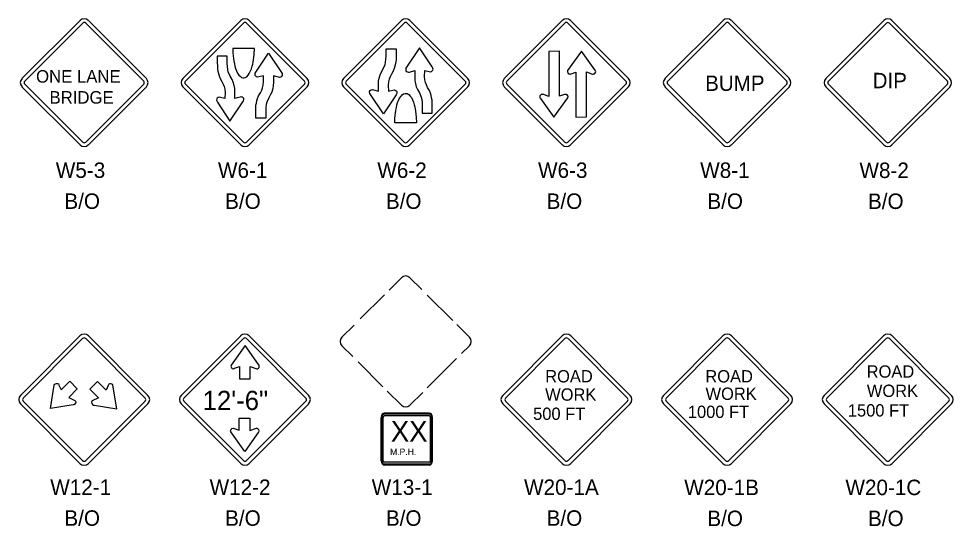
# Model space of a CAD drawing. Extents: x 10000 to 10794, y 10000 to 10499.
# Drawn here: x 10289.1 to 10500.7, y 10279.5 to 10394.4 of the extents above; entities that cross this region are included whole.
import ezdxf

# ---------------------------------------------------------------- set-up
doc = ezdxf.new("R2010")
doc.units = 0
for name, color, linetype in [('DSIndex', 7, 'Continuous'), ('DSText', 7, 'Continuous'), ('DSTitle', 7, 'Continuous'), ('PlotBorder_dp', 7, 'Continuous')]:
    doc.layers.add(name, color=color, linetype=linetype)

msp = doc.modelspace()

# ---------------------------------------------------------------- linework, layer by layer
at = {"layer": 'DSIndex'}
for p, q in [((10339.42, 10394.02), (10326.27, 10380.87)), ((10354.44, 10380.87), (10341.29, 10394.02)), ((10362.67, 10380.87), (10375.81, 10394.02)), ((10377.69, 10394.02), (10390.84, 10380.87)), ((10399.07, 10380.87), (10412.21, 10394.02)), ((10414.08, 10394.02), (10427.23, 10380.87)), ((10340.01, 10393.41), (10326.89, 10380.28)), ((10353.82, 10380.28), (10340.69, 10393.41)), ((10363.29, 10380.28), (10376.41, 10393.41)), ((10377.09, 10393.41), (10390.22, 10380.28)), ((10399.68, 10380.28), (10412.81, 10393.41)), ((10413.49, 10393.41), (10426.62, 10380.28)), ((10326.89, 10379.6), (10340.01, 10366.47)), ((10340.69, 10366.47), (10353.82, 10379.6)), ((10376.41, 10366.47), (10363.29, 10379.6)), ((10390.22, 10379.6), (10377.09, 10366.47)), ((10412.81, 10366.47), (10399.68, 10379.6)), ((10426.62, 10379.6), (10413.49, 10366.47)), ((10326.27, 10379), (10339.42, 10365.86)), ((10341.29, 10365.86), (10354.44, 10379)), ((10375.81, 10365.86), (10362.67, 10379.01)), ((10390.84, 10379), (10377.69, 10365.86)), ((10412.21, 10365.86), (10399.07, 10379)), ((10427.23, 10379), (10414.08, 10365.86)), ((10373, 10332.98), (10375.79, 10335.77)), ((10377.71, 10335.77), (10380.41, 10333.07)), ((10366.45, 10326.43), (10371.93, 10331.91)), ((10381.63, 10331.85), (10387.41, 10326.07)), ((10362.32, 10322.3), (10365.08, 10325.05)), ((10388.3, 10325.18), (10391.18, 10322.3)), ((10289.53, 10309.13), (10303, 10322.61)), ((10290.15, 10308.52), (10303.61, 10321.98)), ((10304.31, 10321.98), (10317.77, 10308.52)), ((10304.92, 10322.61), (10318.39, 10309.13)), ((10325.92, 10309.13), (10339.4, 10322.61)), ((10326.55, 10308.52), (10340.01, 10321.98)), ((10340.7, 10321.98), (10354.16, 10308.52)), ((10341.31, 10322.61), (10354.79, 10309.13)), ((10364.78, 10317.92), (10362.32, 10320.38)), ((10391.18, 10320.38), (10389.38, 10318.58)), ((10371.6, 10311.1), (10365.97, 10316.73)), ((10388.29, 10317.48), (10381.65, 10310.85)), ((10375.79, 10306.91), (10372.59, 10310.11)), ((10380.62, 10309.82), (10377.71, 10306.91)), ((10303, 10293.74), (10289.53, 10307.22)), ((10303.61, 10294.37), (10290.15, 10307.83)), ((10317.77, 10307.83), (10304.31, 10294.37)), ((10318.39, 10307.22), (10304.92, 10293.74)), ((10339.4, 10293.74), (10325.92, 10307.22)), ((10340.01, 10294.37), (10326.55, 10307.83)), ((10354.16, 10307.83), (10340.7, 10294.37)), ((10354.79, 10307.22), (10341.31, 10293.74)), ((10382.1, 10305.13), (10371.91, 10305.13)), ((10371.19, 10294.33), (10371.19, 10304.15)), ((10371.37, 10294.33), (10371.37, 10304.15)), ((10371.67, 10294.33), (10371.67, 10304.15)), ((10382.1, 10304.88), (10371.91, 10304.88)), ((10382.1, 10304.47), (10371.91, 10304.47)), ((10382.35, 10294.33), (10382.35, 10304.15)), ((10382.65, 10294.33), (10382.65, 10304.15)), ((10382.83, 10294.33), (10382.83, 10304.15)), ((10382.1, 10294), (10371.91, 10294)), ((10382.1, 10293.59), (10371.91, 10293.59)), ((10382.1, 10293.35), (10371.91, 10293.35))]:
    msp.add_line(p, q, dxfattribs=at)
for points in [[(10342.49, 10387.67), (10337.6, 10387.67), (10337.61, 10387.36), (10337.64, 10386.8), (10337.7, 10385.96), (10337.75, 10385.49), (10337.84, 10384.81), (10337.96, 10384.25), (10338.08, 10383.63), (10338.24, 10383.1), (10338.48, 10382.62), (10338.68, 10382.1), (10339.01, 10381.66), (10339.24, 10381.39), (10339.57, 10381.11), (10339.85, 10381.04), (10340.08, 10381.04), (10340.39, 10381.1), (10340.79, 10381.28), (10341.05, 10381.64), (10341.35, 10382), (10341.57, 10382.48), (10341.82, 10383.03), (10341.98, 10383.66), (10342.13, 10384.12), (10342.22, 10384.56), (10342.32, 10385.06), (10342.38, 10385.72), (10342.44, 10386.4)], [(10372.31, 10387.61), (10374.57, 10387.61), (10374.57, 10385.89), (10374.56, 10385.55), (10374.56, 10385.04), (10374.53, 10384.69), (10374.43, 10384.18), (10374.31, 10383.64), (10374.16, 10383.13), (10373.94, 10382.52), (10373.51, 10381.82), (10373.24, 10381.25), (10373.04, 10380.72), (10372.87, 10380.11), (10372.82, 10379.35), (10372.85, 10377.99), (10374.18, 10378.3), (10374.4, 10378.21), (10374.58, 10378.08), (10374.72, 10377.91), (10374.75, 10377.64), (10374.72, 10377.45), (10374.56, 10377.15), (10371.71, 10372.87), (10368.61, 10377.46), (10368.58, 10377.76), (10368.58, 10377.96), (10368.68, 10378.16), (10368.94, 10378.3), (10369.21, 10378.37), (10369.43, 10378.32), (10370.58, 10377.98), (10370.58, 10379.42), (10370.63, 10380.28), (10370.75, 10380.91), (10370.95, 10381.69), (10371.21, 10382.26), (10371.65, 10383.03), (10372.09, 10384.01), (10372.21, 10384.52), (10372.29, 10385.23), (10372.31, 10385.91)], [(10380.51, 10373.04), (10382.78, 10373.04), (10382.78, 10374.76), (10382.77, 10375.1), (10382.77, 10375.61), (10382.73, 10375.96), (10382.63, 10376.47), (10382.51, 10377.01), (10382.36, 10377.52), (10382.14, 10378.13), (10381.72, 10378.83), (10381.45, 10379.4), (10381.24, 10379.93), (10381.07, 10380.54), (10381.02, 10381.3), (10381.05, 10382.66), (10382.38, 10382.35), (10382.6, 10382.44), (10382.78, 10382.57), (10382.92, 10382.74), (10382.95, 10383.01), (10382.92, 10383.2), (10382.77, 10383.5), (10379.91, 10387.78), (10376.82, 10383.19), (10376.79, 10382.89), (10376.79, 10382.69), (10376.89, 10382.49), (10377.14, 10382.35), (10377.41, 10382.28), (10377.63, 10382.33), (10378.79, 10382.67), (10378.79, 10381.23), (10378.84, 10380.37), (10378.95, 10379.74), (10379.16, 10378.96), (10379.41, 10378.39), (10379.85, 10377.62), (10380.29, 10376.64), (10380.41, 10376.13), (10380.5, 10375.42), (10380.51, 10374.74)], [(10336.37, 10385.96), (10334.1, 10385.96), (10334.1, 10384.24), (10334.11, 10383.9), (10334.11, 10383.39), (10334.15, 10383.03), (10334.25, 10382.53), (10334.37, 10381.98), (10334.52, 10381.48), (10334.74, 10380.87), (10335.16, 10380.17), (10335.44, 10379.59), (10335.64, 10379.07), (10335.81, 10378.46), (10335.86, 10377.7), (10335.83, 10376.34), (10334.5, 10376.65), (10334.28, 10376.56), (10334.1, 10376.43), (10333.96, 10376.26), (10333.93, 10375.99), (10333.96, 10375.8), (10334.11, 10375.49), (10336.97, 10371.22), (10340.06, 10375.81), (10340.1, 10376.1), (10340.1, 10376.31), (10339.99, 10376.51), (10339.74, 10376.65), (10339.47, 10376.71), (10339.25, 10376.66), (10338.1, 10376.32), (10338.1, 10377.77), (10338.05, 10378.63), (10337.93, 10379.26), (10337.72, 10380.04), (10337.47, 10380.61), (10337.03, 10381.37), (10336.59, 10382.36), (10336.47, 10382.87), (10336.38, 10383.58), (10336.37, 10384.26)], [(10345.08, 10371.88), (10342.81, 10371.88), (10342.81, 10373.6), (10342.82, 10373.94), (10342.82, 10374.45), (10342.86, 10374.8), (10342.96, 10375.31), (10343.08, 10375.85), (10343.23, 10376.36), (10343.45, 10376.97), (10343.87, 10377.66), (10344.15, 10378.24), (10344.35, 10378.77), (10344.52, 10379.38), (10344.57, 10380.14), (10344.54, 10381.49), (10343.21, 10381.19), (10342.99, 10381.27), (10342.81, 10381.41), (10342.67, 10381.58), (10342.64, 10381.85), (10342.67, 10382.04), (10342.82, 10382.34), (10345.68, 10386.61), (10348.77, 10382.03), (10348.81, 10381.73), (10348.81, 10381.53), (10348.7, 10381.33), (10348.45, 10381.19), (10348.18, 10381.12), (10347.96, 10381.17), (10346.81, 10381.51), (10346.81, 10380.07), (10346.76, 10379.21), (10346.64, 10378.58), (10346.43, 10377.8), (10346.18, 10377.22), (10345.74, 10376.46), (10345.3, 10375.48), (10345.18, 10374.97), (10345.09, 10374.26), (10345.08, 10373.58)], [(10411.56, 10387.03), (10409.15, 10387), (10409.15, 10376.81), (10407.81, 10377.29), (10407.67, 10377.28), (10407.45, 10377.24), (10407.27, 10377.1), (10407.14, 10376.93), (10407.09, 10376.75), (10407.09, 10376.57), (10407.18, 10376.44), (10407.24, 10376.37), (10410.29, 10372.08), (10413.44, 10376.49), (10413.48, 10376.57), (10413.53, 10376.7), (10413.53, 10376.88), (10413.44, 10376.97), (10413.3, 10377.15), (10413.17, 10377.28), (10412.99, 10377.28), (10412.67, 10377.23), (10411.56, 10376.84)], [(10417.7, 10372.16), (10417.7, 10382.35), (10419.04, 10381.87), (10419.2, 10381.84), (10419.38, 10381.89), (10419.51, 10381.93), (10419.6, 10382.02), (10419.74, 10382.2), (10419.78, 10382.38), (10419.74, 10382.6), (10419.61, 10382.8), (10416.56, 10387.08), (10413.41, 10382.67), (10413.39, 10382.56), (10413.35, 10382.38), (10413.44, 10382.2), (10413.53, 10382.02), (10413.66, 10381.93), (10413.84, 10381.89), (10413.97, 10381.84), (10414.18, 10381.94), (10415.29, 10382.32), (10415.29, 10372.13)], [(10379.18, 10370.87), (10374.28, 10370.87), (10374.3, 10371.18), (10374.32, 10371.74), (10374.38, 10372.58), (10374.44, 10373.05), (10374.53, 10373.73), (10374.65, 10374.29), (10374.77, 10374.91), (10374.93, 10375.44), (10375.16, 10375.92), (10375.37, 10376.44), (10375.69, 10376.88), (10375.93, 10377.15), (10376.25, 10377.43), (10376.53, 10377.5), (10376.77, 10377.5), (10377.08, 10377.44), (10377.48, 10377.26), (10377.74, 10376.9), (10378.03, 10376.54), (10378.26, 10376.06), (10378.51, 10375.51), (10378.67, 10374.88), (10378.82, 10374.42), (10378.9, 10373.98), (10379.01, 10373.48), (10379.07, 10372.82), (10379.12, 10372.14)], [(10339.14, 10312.91), (10341.55, 10312.91), (10341.55, 10315.67), (10343.05, 10315.16), (10343.2, 10315.17), (10343.42, 10315.27), (10343.55, 10315.47), (10343.6, 10315.74), (10343.54, 10316.03), (10343.46, 10316.11), (10340.41, 10320.4), (10337.26, 10315.99), (10337.16, 10315.78), (10337.23, 10315.61), (10337.33, 10315.39), (10337.5, 10315.22), (10337.77, 10315.15), (10338.03, 10315.26), (10339.14, 10315.64)], [(10300.7, 10312.32), (10302.4, 10310.62), (10300.45, 10308.67), (10301.87, 10307.97), (10301.97, 10307.86), (10302.05, 10307.63), (10302, 10307.39), (10301.85, 10307.17), (10301.6, 10307.01), (10301.48, 10307), (10296.3, 10306.13), (10297.19, 10311.47), (10297.27, 10311.7), (10297.43, 10311.77), (10297.66, 10311.85), (10297.9, 10311.85), (10298.14, 10311.71), (10298.25, 10311.45), (10298.77, 10310.39)], [(10306.98, 10312.26), (10305.27, 10310.55), (10307.22, 10308.6), (10305.8, 10307.9), (10305.71, 10307.79), (10305.62, 10307.56), (10305.67, 10307.32), (10305.83, 10307.1), (10306.08, 10306.94), (10306.19, 10306.94), (10311.38, 10306.06), (10310.48, 10311.41), (10310.41, 10311.63), (10310.24, 10311.7), (10310.01, 10311.78), (10309.77, 10311.78), (10309.54, 10311.64), (10309.42, 10311.38), (10308.91, 10310.33)], [(10339.04, 10303.95), (10341.45, 10303.95), (10341.45, 10301.19), (10342.95, 10301.7), (10343.09, 10301.69), (10343.31, 10301.58), (10343.45, 10301.38), (10343.5, 10301.11), (10343.43, 10300.83), (10343.36, 10300.74), (10340.31, 10296.46), (10337.16, 10300.87), (10337.06, 10301.08), (10337.13, 10301.25), (10337.23, 10301.47), (10337.39, 10301.64), (10337.66, 10301.7), (10337.93, 10301.6), (10339.04, 10301.22)]]:
    msp.add_lwpolyline(points, close=True, dxfattribs=at)
for centre, radius, start, end in [((10340.35, 10393.08), 1.32, 45, 135), ((10376.75, 10393.08), 1.32, 45, 135), ((10413.15, 10393.08), 1.32, 45, 135), ((10340.35, 10393.07), 0.478, 45, 135), ((10376.75, 10393.07), 0.478, 45, 135), ((10413.15, 10393.07), 0.478, 45, 135), ((10327.21, 10379.94), 1.32, 135, 225), ((10327.22, 10379.94), 0.478, 135, 225), ((10353.49, 10379.94), 0.478, 315, 45), ((10353.49, 10379.94), 1.32, 315, 45), ((10363.61, 10379.94), 1.32, 135, 225), ((10363.62, 10379.94), 0.478, 135, 225), ((10389.89, 10379.94), 0.478, 315, 45), ((10389.89, 10379.94), 1.32, 315, 45), ((10400.01, 10379.94), 1.32, 135, 225), ((10400.01, 10379.94), 0.478, 135, 225), ((10426.28, 10379.94), 0.478, 315, 45), ((10426.29, 10379.94), 1.32, 315, 45), ((10340.35, 10366.81), 0.478, 225, 315), ((10376.75, 10366.81), 0.478, 225, 315), ((10413.15, 10366.81), 0.478, 225, 315), ((10340.35, 10366.8), 1.32, 225, 315), ((10376.75, 10366.8), 1.32, 225, 315), ((10413.15, 10366.8), 1.32, 225, 315), ((10376.75, 10334.81), 1.36, 45, 135), ((10303.96, 10321.65), 1.36, 45, 135), ((10303.96, 10321.64), 0.49, 45, 135), ((10340.35, 10321.65), 1.36, 45, 135), ((10340.35, 10321.64), 0.49, 45, 135), ((10363.28, 10321.34), 1.36, 135, 225), ((10390.22, 10321.34), 1.36, 315, 45), ((10290.49, 10308.18), 1.36, 135, 225), ((10290.5, 10308.18), 0.49, 135, 225), ((10317.42, 10308.18), 0.49, 315, 45), ((10317.43, 10308.18), 1.36, 315, 45), ((10326.88, 10308.18), 1.36, 135, 225), ((10326.89, 10308.18), 0.49, 135, 225), ((10353.81, 10308.18), 0.49, 315, 45), ((10353.82, 10308.18), 1.36, 315, 45), ((10376.75, 10307.87), 1.36, 225, 315), ((10303.96, 10294.7), 1.36, 225, 315), ((10303.96, 10294.72), 0.49, 225, 315), ((10340.36, 10294.7), 1.36, 225, 315), ((10340.35, 10294.72), 0.49, 225, 315)]:
    msp.add_arc(centre, radius, start, end, dxfattribs=at)
for centre, major_axis, ratio, start_param, end_param in [((10371.91, 10304.15), (0, 0.982), 0.741335, 0, 1.570796), ((10382.1, 10304.15), (0, 0.982), 0.741335, 4.712389, 6.283185), ((10371.91, 10304.15), (0, 0.736), 0.741334, 0, 1.570796), ((10371.91, 10304.15), (0, 0.327), 0.741335, 0, 1.570796), ((10382.1, 10304.15), (0, 0.736), 0.741334, 4.712389, 6.283185), ((10382.1, 10304.15), (0, 0.327), 0.741335, 4.712389, 6.283185), ((10371.91, 10294.33), (0, -0.982), 0.741335, 4.712389, 6.283185), ((10371.91, 10294.33), (0, -0.736), 0.741334, 4.712389, 6.283185), ((10371.91, 10294.33), (0, -0.327), 0.741335, 4.712389, 6.283185), ((10382.1, 10294.33), (0, -0.982), 0.741335, 0, 1.570796), ((10382.1, 10294.33), (0, -0.736), 0.741334, 0, 1.570796), ((10382.1, 10294.33), (0, -0.327), 0.741335, 0, 1.570796)]:
    msp.add_ellipse(centre, major_axis=major_axis, ratio=ratio, start_param=start_param, end_param=end_param, dxfattribs=at)
at = {"layer": 'DSText'}
for p, q in [((10289.88, 10380.87), (10303.03, 10394.02)), ((10304.9, 10394.02), (10318.04, 10380.87)), ((10435.46, 10380.87), (10448.61, 10394.02)), ((10450.48, 10394.02), (10463.62, 10380.87)), ((10471.84, 10380.86), (10484.98, 10394)), ((10486.85, 10394), (10500, 10380.86)), ((10303.03, 10365.86), (10289.88, 10379)), ((10318.04, 10379), (10304.9, 10365.86)), ((10448.61, 10365.86), (10435.46, 10379)), ((10463.62, 10379), (10450.48, 10365.86)), ((10484.98, 10365.84), (10471.84, 10378.99)), ((10500, 10378.99), (10486.85, 10365.84)), ((10398.71, 10309.13), (10412.19, 10322.61)), ((10414.11, 10322.61), (10427.58, 10309.13)), ((10435.1, 10309.13), (10448.58, 10322.61)), ((10450.49, 10322.61), (10463.96, 10309.13)), ((10471.48, 10309.13), (10484.95, 10322.61)), ((10486.87, 10322.61), (10500.34, 10309.13)), ((10412.19, 10293.74), (10398.71, 10307.22)), ((10427.58, 10307.22), (10414.11, 10293.74)), ((10448.58, 10293.74), (10435.1, 10307.22)), ((10463.96, 10307.22), (10450.49, 10293.74)), ((10484.95, 10293.74), (10471.48, 10307.22)), ((10500.34, 10307.22), (10486.87, 10293.74))]:
    msp.add_line(p, q, dxfattribs=at)
for centre, radius, start, end in [((10303.96, 10393.08), 1.32, 45, 135), ((10449.54, 10393.08), 1.32, 45, 135), ((10485.92, 10393.06), 1.32, 45, 135), ((10290.82, 10379.94), 1.32, 135, 225), ((10317.1, 10379.94), 1.32, 315, 45), ((10436.4, 10379.94), 1.32, 135, 225), ((10462.66, 10379.92), 1.32, 315, 45), ((10472.78, 10379.92), 1.32, 135, 225), ((10499.04, 10379.91), 1.32, 315, 45), ((10303.96, 10366.8), 1.32, 225, 315), ((10449.54, 10366.8), 1.32, 225, 315), ((10485.92, 10366.78), 1.32, 225, 315), ((10413.15, 10321.65), 1.36, 45, 135), ((10449.53, 10321.65), 1.36, 45, 135), ((10485.91, 10321.65), 1.36, 45, 135), ((10399.68, 10308.18), 1.36, 135, 225), ((10426.62, 10308.18), 1.36, 315, 45), ((10436.06, 10308.18), 1.36, 135, 225), ((10463, 10308.18), 1.36, 315, 45), ((10472.44, 10308.18), 1.36, 135, 225), ((10499.38, 10308.18), 1.36, 315, 45), ((10413.15, 10294.7), 1.36, 225, 315), ((10449.53, 10294.7), 1.36, 225, 315), ((10485.91, 10294.7), 1.36, 225, 315)]:
    msp.add_arc(centre, radius, start, end, dxfattribs=at)
at = {"layer": 'DSTitle'}
for p, q in [((10290.49, 10380.28), (10303.62, 10393.41)), ((10304.3, 10393.41), (10317.43, 10380.28)), ((10436.07, 10380.28), (10449.2, 10393.41)), ((10449.88, 10393.41), (10463.01, 10380.28)), ((10472.45, 10380.26), (10485.58, 10393.39)), ((10486.26, 10393.39), (10499.39, 10380.26)), ((10303.62, 10366.47), (10290.49, 10379.6)), ((10317.43, 10379.6), (10304.3, 10366.47)), ((10449.2, 10366.47), (10436.07, 10379.6)), ((10463.01, 10379.6), (10449.88, 10366.47)), ((10485.58, 10366.45), (10472.45, 10379.58)), ((10499.39, 10379.58), (10486.26, 10366.45)), ((10399.34, 10308.52), (10412.8, 10321.98)), ((10413.5, 10321.98), (10426.95, 10308.52)), ((10435.73, 10308.52), (10449.18, 10321.98)), ((10449.88, 10321.98), (10463.34, 10308.52)), ((10472.1, 10308.52), (10485.56, 10321.98)), ((10486.26, 10321.98), (10499.71, 10308.52)), ((10412.8, 10294.37), (10399.34, 10307.83)), ((10426.95, 10307.83), (10413.5, 10294.37)), ((10449.18, 10294.37), (10435.73, 10307.83)), ((10463.34, 10307.83), (10449.88, 10294.37)), ((10485.56, 10294.37), (10472.1, 10307.83)), ((10499.71, 10307.83), (10486.26, 10294.37))]:
    msp.add_line(p, q, dxfattribs=at)
for centre, radius, start, end in [((10303.96, 10393.07), 0.478, 45, 135), ((10449.54, 10393.07), 0.478, 45, 135), ((10485.92, 10393.06), 0.478, 45, 135), ((10290.83, 10379.94), 0.478, 135, 225), ((10317.09, 10379.94), 0.478, 315, 45), ((10436.41, 10379.94), 0.478, 135, 225), ((10462.66, 10379.92), 0.478, 315, 45), ((10472.78, 10379.92), 0.478, 135, 225), ((10499.03, 10379.91), 0.478, 315, 45), ((10303.96, 10366.81), 0.478, 225, 315), ((10449.54, 10366.81), 0.478, 225, 315), ((10485.92, 10366.79), 0.478, 225, 315), ((10413.15, 10321.64), 0.49, 45, 135), ((10449.53, 10321.64), 0.49, 45, 135), ((10485.91, 10321.64), 0.49, 45, 135), ((10399.69, 10308.18), 0.49, 135, 225), ((10426.61, 10308.18), 0.49, 315, 45), ((10436.07, 10308.18), 0.49, 135, 225), ((10462.99, 10308.18), 0.49, 315, 45), ((10472.45, 10308.18), 0.49, 135, 225), ((10499.37, 10308.18), 0.49, 315, 45), ((10413.15, 10294.72), 0.49, 225, 315), ((10449.53, 10294.72), 0.49, 225, 315), ((10485.91, 10294.72), 0.49, 225, 315)]:
    msp.add_arc(centre, radius, start, end, dxfattribs=at)

# ---------------------------------------------------------------- texts
at = {"layer": 'DSIndex'}
for s, height, p in [('W6-1', 3.5, (10334.25, 10358.36)), ('W6-2', 3.5, (10370.33, 10358.36)), ('W6-3', 3.5, (10406.72, 10358.36)), ('B/O', 3.5, (10335.87, 10351.35)), ('B/O', 3.5, (10372.27, 10351.35)), ('B/O', 3.5, (10408.66, 10351.35)), ('12\'-6"', 4.353, (10330.78, 10305.82)), ('XX', 4.644, (10373.4, 10298.68)), ('M.P.H.', 1.451, (10373.22, 10295.64)), ('W12-1', 3.5, (10296.28, 10286.6)), ('W12-2', 3.5, (10332.36, 10286.6)), ('W13-1', 3.5, (10369.07, 10286.6)), ('B/O', 3.5, (10299.48, 10279.61)), ('B/O', 3.5, (10335.87, 10279.61)), ('B/O', 3.5, (10372.27, 10279.61))]:
    msp.add_text(s, height=height, dxfattribs=at).set_placement(p)
at = {"layer": 'PlotBorder_dp'}
for s, height, p in [('ONE LANE', 2.831, (10293.07, 10379.93)), ('BUMP', 3.482, (10444.55, 10378.06)), ('DIP', 3.482, (10482.47, 10378.67)), ('BRIDGE', 2.831, (10296.12, 10375.18)), ('W5-3', 3.5, (10297.54, 10358.36)), ('W8-1', 3.5, (10443.43, 10358.36)), ('W8-2', 3.5, (10479.49, 10358.34)), ('B/O', 3.5, (10299.48, 10351.35)), ('B/O', 3.5, (10445.05, 10351.35)), ('B/O', 3.5, (10481.42, 10351.33)), ('ROAD', 2.786, (10481.12, 10313.14)), ('ROAD', 2.786, (10408.34, 10312.07)), ('ROAD', 2.786, (10444.6, 10312.06)), ('WORK', 2.786, (10481.16, 10308.78)), ('WORK', 2.786, (10408.33, 10307.93)), ('WORK', 2.786, (10444.64, 10308.11)), ('1500 FT', 2.786, (10476.86, 10304.35)), ('500 FT', 2.786, (10405.61, 10303.58)), ('1000 FT', 2.786, (10440.64, 10304.02)), ('W20-1A', 3.5, (10403.55, 10286.6)), ('W20-1B', 3.5, (10439.82, 10286.55)), ('W20-1C', 3.5, (10476.32, 10286.55)), ('B/O', 3.5, (10408.66, 10279.61)), ('B/O', 3.5, (10445.05, 10279.54)), ('B/O', 3.5, (10481.42, 10279.54))]:
    msp.add_text(s, height=height, dxfattribs=at).set_placement(p)

doc.saveas('drawing.dxf')
